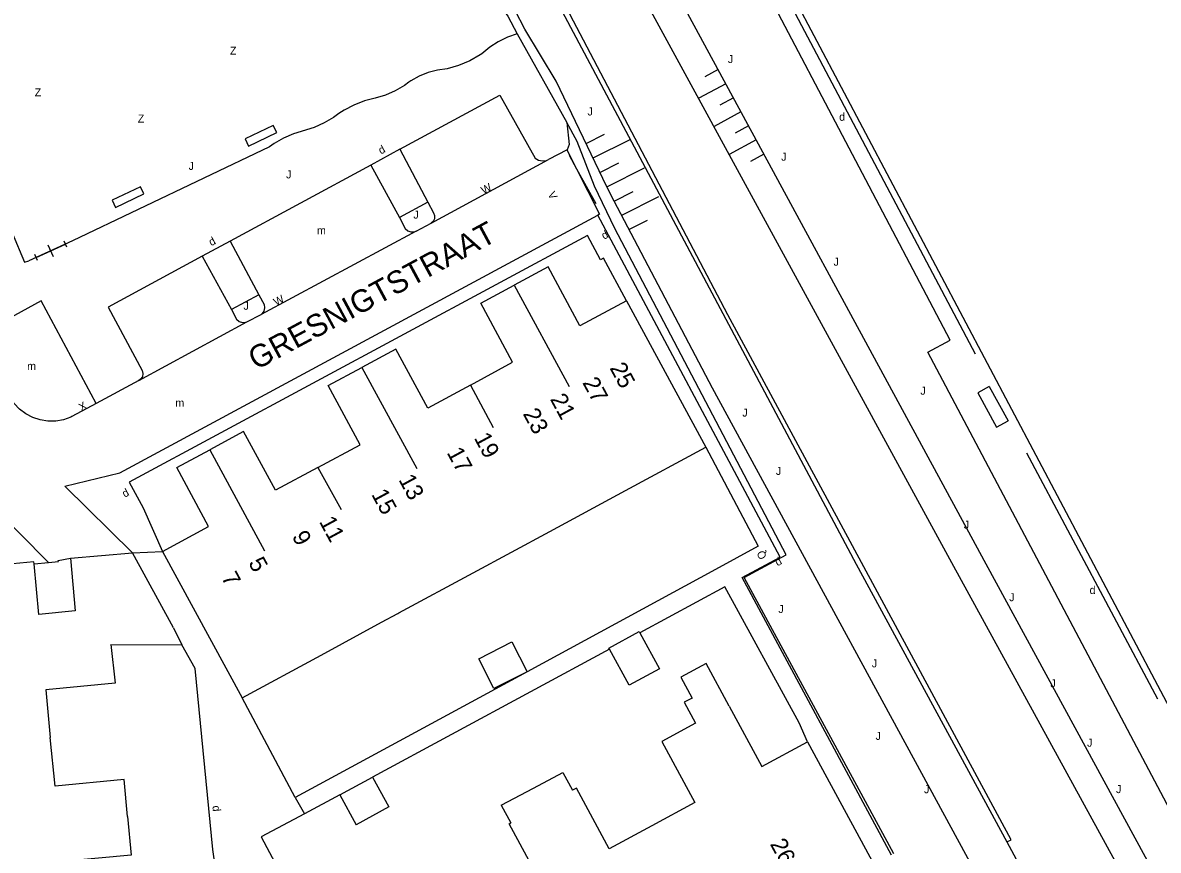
# Model space of a CAD drawing. Extents: x 134999 to 136502, y 457398 to 459002.
# Drawn here: x 136040.9 to 136111.8, y 457649.3 to 457701.1 of the extents above; entities that cross this region are included whole.
import ezdxf

# ---------------------------------------------------------------- set-up
doc = ezdxf.new("R2010")
doc.units = 0
for name, color, linetype in [('RI_DGTB_15', 7, 'Continuous'), ('RI_DGTB_18', 7, 'Continuous'), ('RI_DGTB_23', 7, 'Continuous'), ('RI_DGTB_29', 7, 'Continuous'), ('RI_DGTB_30', 7, 'Continuous'), ('RI_DGTB_31', 7, 'Continuous'), ('RI_DGTB_32', 7, 'Continuous'), ('RI_DGTB_35', 7, 'Continuous'), ('RI_DGTB_36', 7, 'Continuous'), ('RI_DGTB_37', 7, 'Continuous'), ('RI_DGTB_4', 7, 'Continuous'), ('RI_DGTB_43', 7, 'Continuous'), ('RI_DGTB_48', 7, 'Continuous'), ('RI_DGTB_49', 7, 'Continuous'), ('RI_DGTB_5', 7, 'Continuous'), ('RI_DGTB_53', 7, 'Continuous'), ('RI_DGTB_54', 7, 'Continuous'), ('RI_DGTB_55', 7, 'Continuous'), ('RI_DGTB_58', 7, 'Continuous'), ('RI_DGTB_6', 7, 'Continuous')]:
    doc.layers.add(name, color=color, linetype=linetype)

msp = doc.modelspace()

# ---------------------------------------------------------------- linework, layer by layer
at = {"layer": 'RI_DGTB_15'}
for p, q in [((136071.614, 457684.654), (136075.039, 457678.329)), ((136062.104, 457679.513), (136065.529, 457673.191)), ((136068.875, 457678.411), (136070.307, 457675.772)), ((136052.602, 457674.377), (136056.025, 457668.056)), ((136059.344, 457673.258), (136060.807, 457670.637))]:
    msp.add_line(p, q, dxfattribs=at)
at = {"layer": 'RI_DGTB_18'}
for p, q in [((136084.352, 457698.122), (136083.51, 457697.666)), ((136084.828, 457697.242), (136083.143, 457696.331)), ((136085.303, 457696.363), (136084.461, 457695.907)), ((136085.779, 457695.483), (136084.095, 457694.572)), ((136076.103, 457693.508), (136077.259, 457694.084)), ((136086.255, 457694.603), (136085.412, 457694.148)), ((136076.549, 457692.613), (136078.861, 457693.765)), ((136086.73, 457693.724), (136085.046, 457692.813)), ((136087.206, 457692.844), (136086.364, 457692.389)), ((136076.995, 457691.718), (136078.151, 457692.294)), ((136077.441, 457690.823), (136079.753, 457691.975)), ((136077.851, 457689.91), (136079.043, 457690.504)), ((136078.333, 457689.033), (136080.645, 457690.185)), ((136078.779, 457688.138), (136079.935, 457688.714))]:
    msp.add_line(p, q, dxfattribs=at)
for points in [[(136063.968, 457736.473), (136078.546, 457708.97), (136080.695, 457704.886), (136101.064, 457667.235), (136120.849, 457630.867), (136122.138, 457628.364), (136122.744, 457627.053)], [(136123.733, 457602.393), (136120.854, 457608.26), (136113.226, 457622.174), (136108.621, 457631.115), (136104.943, 457638.994), (136101.264, 457646.446), (136083.989, 457678.217), (136077.85, 457689.911), (136077.399, 457690.806), (136074.236, 457697.397), (136072.278, 457700.64), (136071.067, 457702.994), (136069.704, 457704.875), (136065.561, 457709.646), (136062.974, 457712.597), (136061.189, 457715.009), (136060.471, 457716.789), (136060.125, 457718.639), (136060.201, 457718.837), (136061.046, 457719.422)]]:
    msp.add_lwpolyline(points, dxfattribs=at)
at = {"layer": 'RI_DGTB_23'}
msp.add_lwpolyline([(136057.934, 457652.657), (136058.51, 457651.627)], dxfattribs=at)
at = {"layer": 'RI_DGTB_32'}
for points in [[(136055.02, 457693.339), (136056.781, 457694.183), (136056.565, 457694.634), (136054.804, 457693.79), (136055.02, 457693.339)], [(136046.72, 457689.506), (136048.481, 457690.352), (136048.264, 457690.803), (136046.503, 457689.957), (136046.72, 457689.506)]]:
    msp.add_lwpolyline(points, dxfattribs=at)
at = {"layer": 'RI_DGTB_4'}
for p, q in [((136078.62, 457683.686), (136083.581, 457674.541)), ((136078.56, 457671.826), (136083.581, 457674.541)), ((136073.835, 457669.271), (136078.56, 457671.826)), ((136069.053, 457666.685), (136073.835, 457669.271)), ((136049.652, 457668.024), (136054.613, 457658.877)), ((136064.413, 457664.176), (136069.053, 457666.685)), ((136059.55, 457661.547), (136063.331, 457663.591)), ((136064.342, 457664.138), (136064.413, 457664.176)), ((136054.613, 457658.877), (136059.55, 457661.547)), ((136089.942, 457656.128), (136094.102, 457648.437)), ((136072.822, 457653.237), (136074.651, 457654.204)), ((136070.796, 457652.166), (136072.822, 457653.237))]:
    msp.add_line(p, q, dxfattribs=at)
for points in [[(136078.62, 457683.686), (136075.717, 457682.116), (136073.725, 457685.795), (136071.614, 457684.654)], [(136068.875, 457678.411), (136071.512, 457679.843), (136069.52, 457683.522), (136071.614, 457684.654)], [(136068.875, 457678.411), (136066.213, 457676.965), (136064.215, 457680.654), (136062.104, 457679.513)], [(136059.344, 457673.258), (136061.998, 457674.687), (136060.001, 457678.377), (136062.104, 457679.513)], [(136059.344, 457673.258), (136056.706, 457671.837), (136054.713, 457675.518), (136052.602, 457674.377)], [(136049.652, 457668.024), (136052.528, 457669.581), (136050.537, 457673.261), (136052.602, 457674.377)], [(136041.624, 457667.236), (136041.611, 457667.371), (136032.854, 457666.534), (136033.399, 457660.905)], [(136044.197, 457664.3), (136041.927, 457664.084), (136041.624, 457667.236)], [(136046.425, 457662.201), (136046.683, 457659.795), (136042.349, 457659.382), (136042.637, 457656.404)], [(136085.042, 457658.351), (136087.081, 457654.585), (136089.942, 457656.128)], [(136047.463, 457651.455), (136047.244, 457653.77), (136042.932, 457653.359), (136042.637, 457656.404)], [(136080.833, 457656.149), (136082.897, 457652.329), (136080.207, 457650.878)], [(136080.207, 457650.878), (136077.55, 457649.446), (136075.505, 457653.23), (136075.25, 457653.095)], [(136047.463, 457651.455), (136047.69, 457649.05), (136043.389, 457648.64), (136043.678, 457645.65)], [(136070.681, 457645.738), (136073.36, 457647.185), (136071.297, 457651.005), (136071.395, 457651.057)]]:
    msp.add_lwpolyline(points, dxfattribs=at)
at = {"layer": 'RI_DGTB_48'}
for p, q in [((136071.805, 457700.347), (136074.894, 457694.814)), ((136044.032, 457687.422), (136041.296, 457686.172)), ((136041.751, 457686.38), (136043.577, 457687.214)), ((136042.831, 457686.432), (136042.497, 457687.163)), ((136043.661, 457687.032), (136043.494, 457687.397)), ((136041.835, 457686.197), (136041.667, 457686.563))]:
    msp.add_line(p, q, dxfattribs=at)
for points in [[(136057.944, 457716.231), (136065.689, 457708.481), (136067.693, 457706.277), (136069.486, 457703.938), (136071.216, 457701.453), (136071.805, 457700.347)], [(136035.903, 457701.937), (136036.459, 457699.463), (136039.461, 457689.758), (136041.032, 457686.09), (136041.296, 457686.172)], [(136071.805, 457700.347), (136071.198, 457700.143), (136070.62, 457699.866), (136070.082, 457699.518), (136069.586, 457699.101), (136069.489, 457699.039), (136068.833, 457698.675), (136068.143, 457698.382), (136067.425, 457698.165), (136066.826, 457698.094), (136066.242, 457697.944), (136065.683, 457697.719), (136065.158, 457697.422), (136065.032, 457697.335), (136064.752, 457697.134), (136064.178, 457696.796), (136063.568, 457696.529), (136062.931, 457696.337), (136062.256, 457696.161), (136061.605, 457695.909), (136060.987, 457695.584), (136060.656, 457695.37), (136060.333, 457695.135), (136059.747, 457694.789), (136059.125, 457694.513), (136057.824, 457694.114), (136057.2, 457693.84), (136056.613, 457693.495), (136056.326, 457693.29), (136044.032, 457687.422)], [(136095.326, 457649.134), (136085.975, 457666.385), (136088.603, 457667.804), (136077.9, 457688.196), (136076.632, 457690.84), (136075.549, 457693.64), (136074.894, 457694.814)]]:
    msp.add_lwpolyline(points, dxfattribs=at)
at = {"layer": 'RI_DGTB_49'}
for p, q in [((136075.046, 457692.771), (136075.512, 457691.929)), ((136075.512, 457691.929), (136076.717, 457689.752)), ((136111.816, 457658.79), (136103.636, 457674.154))]:
    msp.add_line(p, q, dxfattribs=at)
msp.add_lwpolyline([(136163.271, 457715.566), (136145.975, 457748.321), (136082.5, 457714.246), (136100.413, 457680.372)], dxfattribs=at)
at = {"layer": 'RI_DGTB_5'}
for p, q in [((136063.331, 457663.591), (136064.342, 457664.138)), ((136082.939, 457657.288), (136080.833, 457656.149)), ((136074.651, 457654.204), (136075.25, 457653.095)), ((136070.796, 457652.166), (136071.395, 457651.057))]:
    msp.add_line(p, q, dxfattribs=at)
msp.add_lwpolyline([(136085.042, 457658.351), (136083.596, 457661.022), (136082.013, 457660.165), (136082.721, 457658.858), (136082.233, 457658.595), (136082.939, 457657.288)], dxfattribs=at)
at = {"layer": 'RI_DGTB_53'}
msp.add_lwpolyline([(136045.503, 457677.26), (136042.068, 457683.668), (136037.692, 457681.291)], dxfattribs=at)
at = {"layer": 'RI_DGTB_54'}
for p, q in [((136064.474, 457693.143), (136062.657, 457692.162)), ((136064.474, 457693.143), (136066.209, 457689.845)), ((136074.916, 457693.11), (136073.755, 457692.501)), ((136075.512, 457691.929), (136074.916, 457693.11)), ((136062.657, 457692.162), (136053.877, 457687.413)), ((136062.657, 457692.162), (136064.442, 457688.882)), ((136066.422, 457688.531), (136073.755, 457692.501)), ((136066.209, 457689.845), (136064.442, 457688.882)), ((136065.487, 457688.021), (136066.422, 457688.531)), ((136088.219, 457667.656), (136076.842, 457689.023)), ((136065.487, 457688.021), (136055.8, 457682.827)), ((136053.877, 457687.413), (136052.133, 457686.471)), ((136053.877, 457687.413), (136055.665, 457684.061)), ((136052.133, 457686.471), (136053.946, 457683.128)), ((136055.665, 457684.061), (136053.946, 457683.128)), ((136054.922, 457682.36), (136055.8, 457682.827)), ((136048.173, 457678.7), (136054.922, 457682.36)), ((136048.173, 457678.7), (136045.503, 457677.26)), ((136047.764, 457667.94), (136049.652, 457668.024)), ((136041.624, 457667.236), (136042.527, 457667.32)), ((136041.624, 457667.236), (136042.527, 457667.32)), ((136043.138, 457667.459), (136043.9, 457667.591))]:
    msp.add_line(p, q, dxfattribs=at)
for points in [[(136064.474, 457693.143), (136070.709, 457696.515), (136072.922, 457692.587), (136073.139, 457692.465), (136073.382, 457692.418), (136073.629, 457692.451), (136073.755, 457692.501)], [(136074.894, 457694.814), (136075.053, 457693.45), (136074.916, 457693.11)], [(136075.512, 457691.929), (136076.949, 457689.081), (136076.842, 457689.023)], [(136066.209, 457689.845), (136066.564, 457689.171), (136066.636, 457688.997), (136066.629, 457688.809), (136066.546, 457688.639), (136066.422, 457688.531)], [(136047.764, 457667.94), (136043.547, 457672.095), (136046.982, 457672.927), (136076.842, 457689.023)], [(136064.442, 457688.882), (136064.813, 457688.201), (136064.964, 457688.058), (136065.158, 457687.981), (136065.367, 457687.982), (136065.487, 457688.021)], [(136078.62, 457683.686), (136077.187, 457686.332), (136077.011, 457686.228), (136076.201, 457687.761), (136047.561, 457672.341), (136048.441, 457670.754), (136049.652, 457668.024)], [(136052.133, 457686.471), (136046.242, 457683.286), (136048.376, 457679.314), (136048.421, 457679.127), (136048.388, 457678.938), (136048.281, 457678.778), (136048.173, 457678.7)], [(136055.665, 457684.061), (136055.993, 457683.446), (136056.019, 457683.237), (136055.966, 457683.032), (136055.842, 457682.862), (136055.8, 457682.827)], [(136053.946, 457683.128), (136054.272, 457682.527), (136054.435, 457682.391), (136054.636, 457682.324), (136054.848, 457682.336), (136054.922, 457682.36)], [(136045.503, 457677.26), (136043.985, 457676.441), (136043.925, 457676.414), (136043.463, 457676.251), (136042.981, 457676.165), (136042.49, 457676.159), (136042.006, 457676.232), (136041.54, 457676.384), (136041.104, 457676.609), (136040.711, 457676.901), (136040.371, 457677.254), (136037.692, 457681.291)], [(136083.581, 457674.541), (136086.855, 457668.352), (136084.185, 457666.882), (136072.417, 457660.505)], [(136036.129, 457621.417), (136035.193, 457623.469), (136033.047, 457644.948), (136028.7, 457651.634), (136032.618, 457654.264), (136031.54, 457666.407), (136037.069, 457670.528), (136038.902, 457670.973), (136042.527, 457667.32)], [(136042.527, 457667.32), (136043.147, 457667.381), (136043.138, 457667.459)], [(136042.527, 457667.32), (136043.147, 457667.381), (136043.138, 457667.459)], [(136095.176, 457649.049), (136085.856, 457666.382), (136088.219, 457667.656)], [(136089.942, 457656.128), (136089.41, 457657.312), (136084.776, 457665.799), (136079.47, 457662.938)], [(136053.584, 457641.193), (136053.215, 457644.909), (136052.951, 457648.216), (136052.781, 457649.388), (136051.696, 457660.706), (136050.846, 457662.193)], [(136077.565, 457661.911), (136062.756, 457653.926)], [(136072.417, 457660.505), (136057.934, 457652.657)], [(136057.934, 457652.657), (136054.613, 457658.877)], [(136060.717, 457652.81), (136058.51, 457651.627)], [(136058.51, 457651.627), (136055.818, 457650.185), (136060.97, 457640.495)]]:
    msp.add_lwpolyline(points, dxfattribs=at)
at = {"layer": 'RI_DGTB_55'}
for points in [[(136196.949, 457655.273), (136198.574, 457652.238), (136132.548, 457617.637), (136114.894, 457650.812), (136113.527, 457650.075), (136097.454, 457680.477), (136098.843, 457681.226), (136081.172, 457714.844)], [(136193.021, 457650.992), (136136.179, 457620.934), (136135.798, 457620.721), (136135.33, 457620.544), (136134.839, 457620.443), (136134.338, 457620.422), (136133.841, 457620.48), (136133.359, 457620.617), (136132.905, 457620.829), (136132.49, 457621.11), (136132.125, 457621.453), (136131.82, 457621.85), (136131.581, 457622.291), (136084.467, 457711.393)]]:
    msp.add_lwpolyline(points, dxfattribs=at)
at = {"layer": 'RI_DGTB_58'}
msp.add_line((136102.393, 457649.868), (136126.134, 457605.889), dxfattribs=at)
for points in [[(136121.392, 457626.305), (136098.946, 457667.306), (136079.053, 457703.844), (136061.812, 457735.294)], [(136061.046, 457719.422), (136065.038, 457713.791), (136065.756, 457712.77), (136066.538, 457711.796), (136067.381, 457710.875), (136068.281, 457710.01), (136068.315, 457709.979), (136071.033, 457707.079), (136071.927, 457706.016), (136072.758, 457704.904), (136073.524, 457703.746), (136074.222, 457702.546), (136074.784, 457701.446), (136092.963, 457667.226), (136102.393, 457649.868)], [(136102.393, 457649.868), (136102.658, 457650.011), (136084.948, 457682.81), (136074.89, 457701.98)]]:
    msp.add_lwpolyline(points, dxfattribs=at)
at = {"layer": 'RI_DGTB_6'}
for p, q in [((136101.281, 457678.32), (136102.463, 457676.187)), ((136043.9, 457667.591), (136047.764, 457667.94)), ((136050.329, 457663.252), (136047.764, 457667.94)), ((136043.9, 457667.591), (136044.197, 457664.3)), ((136050.329, 457663.252), (136050.846, 457662.193)), ((136046.425, 457662.201), (136050.846, 457662.193)), ((136060.717, 457652.81), (136062.756, 457653.926)), ((136062.756, 457653.926), (136063.779, 457652.057)), ((136060.717, 457652.81), (136061.74, 457650.941)), ((136063.779, 457652.057), (136061.74, 457650.941))]:
    msp.add_line(p, q, dxfattribs=at)
for points in [[(136101.281, 457678.32), (136100.566, 457677.925), (136101.748, 457675.791), (136102.463, 457676.187)], [(136077.565, 457661.911), (136077.525, 457661.983), (136079.425, 457663.02), (136079.47, 457662.938)], [(136079.47, 457662.938), (136080.695, 457660.694), (136078.796, 457659.656)], [(136072.417, 457660.505), (136070.338, 457659.454), (136069.396, 457661.315), (136071.475, 457662.366), (136072.417, 457660.505)], [(136078.796, 457659.656), (136077.565, 457661.911)]]:
    msp.add_lwpolyline(points, dxfattribs=at)

# ---------------------------------------------------------------- texts
at = {"layer": 'RI_DGTB_29'}
for p in [(136091.912, 457694.925), (136107.553, 457665.36)]:
    msp.add_text('d', height=0.5, dxfattribs=at).set_placement(p)
for rotation, p in [(28.39356, (136063.291, 457692.812)), (28.39356, (136052.694, 457687.082)), (28.32623, (136077.224, 457687.489)), (28.32146, (136047.288, 457671.371)), (28.32623, (136088.06, 457667.085)), (275.41028, (136052.76, 457652.121))]:
    msp.add_text('d', height=0.499, rotation=rotation, dxfattribs=at).set_placement(p)
at = {"layer": 'RI_DGTB_30'}
for s, height, rotation, p in [('W', 0.499, 28.29198, (136069.71, 457690.312)), ('V', 0.5, 296.74853, (136073.691, 457690.353)), ('W', 0.499, 28.29198, (136056.751, 457683.337)), ('X', 0.499, 28.36026, (136044.579, 457676.761))]:
    msp.add_text(s, height=height, rotation=rotation, dxfattribs=at).set_placement(p)
at = {"layer": 'RI_DGTB_31'}
for p in [(136084.962, 457698.531), (136076.194, 457695.257), (136088.292, 457692.431), (136051.276, 457691.857), (136057.364, 457691.325), (136065.316, 457688.812), (136091.562, 457685.871), (136054.705, 457683.117), (136096.982, 457677.811), (136085.859, 457676.442), (136087.96, 457672.798), (136099.692, 457669.441), (136102.532, 457664.911), (136088.112, 457664.173), (136093.95, 457660.778), (136105.102, 457659.531), (136094.183, 457656.248), (136107.392, 457655.821), (136097.209, 457652.914), (136109.202, 457652.921)]:
    msp.add_text('J', height=0.5, dxfattribs=at).set_placement(p)
msp.add_text('Q', height=0.5, rotation=118.27645, dxfattribs=at).set_placement((136087.414, 457667.686))
at = {"layer": 'RI_DGTB_32'}
for p in [(136053.858, 457699.053), (136041.663, 457696.451), (136048.103, 457694.817)]:
    msp.add_text('Z', height=0.5, dxfattribs=at).set_placement(p)
at = {"layer": 'RI_DGTB_35'}
for s, rotation, p in [('25', 298.3919, (136077.552, 457679.485)), ('7', 298.3919, (136053.287, 457666.398)), ('26', 298.536, (136087.568, 457649.743))]:
    msp.add_text(s, height=1.054, rotation=rotation, dxfattribs=at).set_placement(p)
at = {"layer": 'RI_DGTB_36'}
for s, rotation, p in [('27', 298.3919, (136075.853, 457678.568)), ('21', 298.3919, (136073.831, 457677.539)), ('23', 298.3919, (136072.133, 457676.622)), ('19', 298.3919, (136069.078, 457675.113)), ('17', 298.3919, (136067.379, 457674.196)), ('13', 298.3919, (136064.366, 457672.506)), ('15', 298.3919, (136062.668, 457671.588)), ('11', 298.3147, (136059.408, 457669.883)), ('9', 298.2991, (136057.708, 457668.969)), ('5', 298.3919, (136054.985, 457667.315))]:
    msp.add_text(s, height=1.054, rotation=rotation, dxfattribs=at).set_placement(p)
at = {"layer": 'RI_DGTB_37'}
msp.add_text('GRESNIGTSTRAAT', height=1.4, rotation=28.32509, dxfattribs=at).set_placement((136055.494, 457679.323))
at = {"layer": 'RI_DGTB_43'}
for p in [(136059.293, 457687.823), (136041.19, 457679.351), (136050.447, 457677.055)]:
    msp.add_text('m', height=0.5, dxfattribs=at).set_placement(p)

doc.saveas('drawing.dxf')
